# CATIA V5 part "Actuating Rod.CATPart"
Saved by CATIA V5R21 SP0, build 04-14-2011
Part number: Actuating Rod
Bounding box of the stored display mesh (mm): x -17.5 to 17.5, y -11.818 to 195.322, z -21 to 21
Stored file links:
  D:\CATIA V5R21 E-RESOURCES\CATIA-V5R21\catia-v5r21-Prts\c12_catia_v5r21_prt\c12_catia_v5r21figr_12-26\Actuating Rod.CATPart
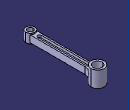
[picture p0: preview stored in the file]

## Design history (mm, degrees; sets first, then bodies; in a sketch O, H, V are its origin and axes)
Body1 (main body)
  Sketch1 on xy-plane, origin (0, 0, 0), H (1, 0, 0), V (0, 1, 0)
    arc A1 centre (0, 0) radius 12 from (-9, 7.9373) to (9, 7.9373) ccw
    arc A2 centre (0, 178) radius 17.5 from (13.5991, 166.9857) to (-13.5991, 166.9857) ccw
    point P1 (0, 178)
    line L1 (9, 154) -> (9, 7.9373)
    point P2 (9, 154)
    point P3 (9, 7.9373)
    arc A3 centre (29.6324, 154) radius 20.6324 from (9, 154) to (13.5991, 166.9857) cw
    point P5 (13.5991, 166.9857)
    point P6 (-13.5991, 166.9857)
    point P7 (-9, 154)
    arc A4 centre (-29.6324, 154) radius 20.6324 from (-9, 154) to (-13.5991, 166.9857) ccw
    point P9 (-9, 7.9373)
    line L2 (-9, 154) -> (-9, 7.9373)
    radius A2 = 17.5
    radius A1 = 12
    distance O P1 = 178
    distance V L1 = 9
    distance P1 P2 V = 24
    coincidence: P1 V
    vertical: L1 V
    tangency: A3 L1, A3 A2
    symmetry: P5 P6 V, P2 P7 V, A3 A4 V, P3 P9 V, L1 L2 V
  Pad1: profile Sketch1, direction (0, 0, 1), length 9, mirrored extent
  Sketch2 on xy-plane, origin (0, 0, 0), H (1, 0, 0), V (0, 1, 0)
    circle A1 centre (0, 0) radius 12
    reference projected arc E1 centre (0, 0) radius 12 from (-9, 7.9373) to (9, 7.9373) ccw from edge of Pad1
    reference projected arc E2 centre (0, 0) radius 12 from (-9, 7.9373) to (9, 7.9373) ccw from edge of Pad1
    reference projected arc E3 centre (0, 0) radius 12 from (-9, 7.9373) to (9, 7.9373) ccw from edge of Pad1
    concentricity: A1 E1, A1 E2
    tangency: A1 E3
  Pad2: profile Sketch2, direction (0, 0, 1), length 12, mirrored extent
  Sketch3 on xy-plane, origin (0, 0, 0), H (1, 0, 0), V (0, 1, 0)
    circle A1 centre (0, 178) radius 17.5
    point P1 (0, 178)
    reference projected arc E1 centre (0, 178) radius 17.5 from (13.5991, 166.9857) to (-13.5991, 166.9857) ccw from edge of Pad1
    reference projected arc E2 centre (0, 178) radius 17.5 from (13.5991, 166.9857) to (-13.5991, 166.9857) ccw from edge of Pad1
    coincidence: P1 V
    concentricity: A1 E1
    tangency: E2 A1
  Pad3: profile Sketch3, direction (0, 0, 1), length 21, mirrored extent
  Sketch4 on xy-plane, origin (0, 0, 0), H (1, 0, 0), V (0, 1, 0)
    circle A1 centre (0, 178) radius 12
    point P1 (0, 178)
    circle A2 centre (0, 0) radius 7.5
    reference projected circle E1 centre (0, 178) radius 17.5 from edge of Pad3
    radius A1 = 12
    radius A2 = 7.5
    coincidence: P1 V
    concentricity: A1 E1
  Pocket1: profile Sketch4, direction (0, 0, -1), length 21, mirrored extent
  Sketch5 on xy-plane, origin (0, 0, 0), H (1, 0, 0), V (0, 1, 0)
    construction line L1 (0, 24) -> (0, 154)
    point P1 (0, 24)
    line L2 (-5, 24) -> (-5, 154)
    line L3 (5, 154) -> (5, 24)
    arc A1 centre (0, 154) radius 5 from (-5, 154) to (5, 154) cw
    arc A2 centre (0, 24) radius 5 from (5, 24) to (-5, 24) cw
    length L1 = 130
    distance H P1 = 24
    radius A1 = 5
    coincidence: P1 V
    vertical: L1 V
    tangency: A1 L2, A2 L2, A1 L3, A2 L3
    parallelism: L1 L2
  Pocket2: profile Sketch5, direction (0, 0, -1), through (limit type 6), opposite side length -2.5
  Mirror1: of Pocket2, Sketch5, about xy-plane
